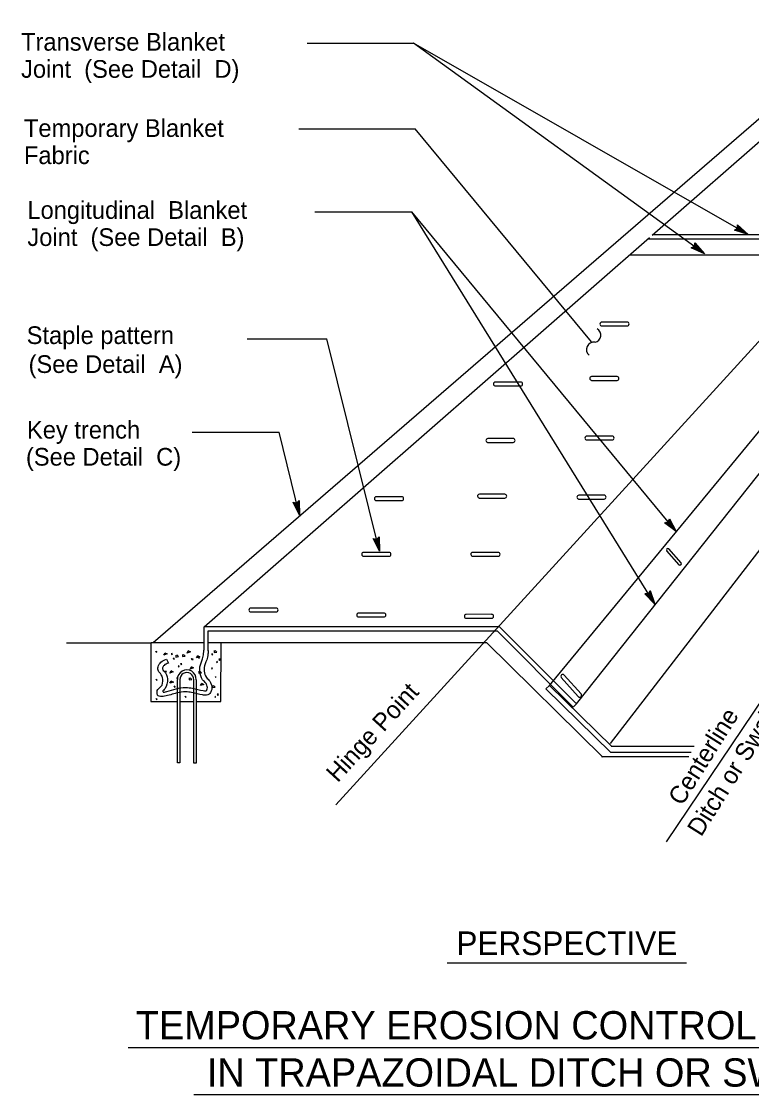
# Model space of a CAD drawing. Extents: x 6712486 to 6713732, y 1869200 to 1869925.
# Drawn here: x 6713055.2 to 6713312.8, y 1869202 to 1869580.8 of the extents above; entities that cross this region are included whole.
import ezdxf

# ---------------------------------------------------------------- set-up
doc = ezdxf.new("R2010")
doc.units = 0
for name, color, linetype in [('56 Stg 3 Anno', 7, 'Continuous'), ('57 Undefined', 7, 'Continuous'), ('60 Nongeo Data', 7, 'Continuous'), ('63 Undefined', 7, 'Continuous')]:
    doc.layers.add(name, color=color, linetype=linetype)

msp = doc.modelspace()

# ---------------------------------------------------------------- linework, layer by layer
at = {"layer": '56 Stg 3 Anno'}
for p, q in [((6713306.74, 1869507.11), (6713307.86, 1869507.74)), ((6713311.62, 1869505.59), (6713306.74, 1869507.11)), ((6713306.74, 1869507.11), (6713306.74, 1869507.11)), ((6713310.62, 1869506.17), (6713307.05, 1869507.28)), ((6713309.63, 1869506.74), (6713307.33, 1869507.45)), ((6713308.63, 1869507.31), (6713307.64, 1869507.62)), ((6713307.86, 1869507.74), (6713307.84, 1869509.04)), ((6713307.84, 1869509.04), (6713307.84, 1869509.04)), ((6713307.84, 1869509.04), (6713311.62, 1869505.59)), ((6713307.85, 1869508.7), (6713310.63, 1869506.16)), ((6713307.85, 1869508.02), (6713308.63, 1869507.31)), ((6713307.87, 1869508.34), (6713309.63, 1869506.74)), ((6713311.62, 1869505.59), (6713311.62, 1869505.59)), ((6713153.29, 1869406.53), (6713151.02, 1869411.12)), ((6713151.02, 1869411.12), (6713151.02, 1869411.12)), ((6713151.02, 1869411.12), (6713152.25, 1869410.73)), ((6713153.01, 1869407.65), (6713151.35, 1869411)), ((6713152.74, 1869408.76), (6713151.67, 1869410.92)), ((6713152.46, 1869409.88), (6713152.01, 1869410.81)), ((6713152.25, 1869410.73), (6713153.18, 1869411.65)), ((6713152.44, 1869410.93), (6713152.46, 1869409.88)), ((6713152.69, 1869411.14), (6713152.74, 1869408.76)), ((6713152.93, 1869411.4), (6713153.01, 1869407.65)), ((6713153.18, 1869411.65), (6713153.18, 1869411.65)), ((6713153.18, 1869411.65), (6713153.29, 1869406.53)), ((6713153.29, 1869406.53), (6713153.29, 1869406.53)), ((6713283.38, 1869404.07), (6713283.82, 1869405.29)), ((6713283.47, 1869404.32), (6713283.94, 1869403.39)), ((6713283.6, 1869404.62), (6713284.68, 1869402.5)), ((6713283.7, 1869404.96), (6713285.41, 1869401.61)), ((6713283.82, 1869405.29), (6713283.82, 1869405.29)), ((6713283.82, 1869405.29), (6713286.14, 1869400.73)), ((6713282.1, 1869403.87), (6713283.38, 1869404.07)), ((6713286.14, 1869400.73), (6713282.1, 1869403.87)), ((6713282.1, 1869403.87), (6713282.1, 1869403.87)), ((6713285.4, 1869401.62), (6713282.46, 1869403.91)), ((6713284.68, 1869402.5), (6713282.77, 1869403.98)), ((6713283.94, 1869403.39), (6713283.13, 1869404.02)), ((6713286.14, 1869400.73), (6713286.14, 1869400.73)), ((6713181.5, 1869393.77), (6713179.24, 1869398.35)), ((6713179.24, 1869398.35), (6713179.24, 1869398.35)), ((6713179.24, 1869398.35), (6713180.47, 1869397.97)), ((6713181.22, 1869394.89), (6713179.57, 1869398.23)), ((6713180.96, 1869396), (6713179.89, 1869398.16)), ((6713180.68, 1869397.12), (6713180.23, 1869398.04)), ((6713180.47, 1869397.97), (6713181.39, 1869398.88)), ((6713180.66, 1869398.17), (6713180.68, 1869397.12)), ((6713180.91, 1869398.38), (6713180.96, 1869396)), ((6713181.15, 1869398.64), (6713181.23, 1869394.88)), ((6713181.39, 1869398.88), (6713181.39, 1869398.88)), ((6713181.39, 1869398.88), (6713181.5, 1869393.77)), ((6713181.5, 1869393.77), (6713181.5, 1869393.77))]:
    msp.add_line(p, q, dxfattribs=at)
for centre, radius, start, end in [((6713257.03, 1869470.05), 2.57, 283.3074, 60.1497), ((6713257.11, 1869464.99), 2.59, 80.6529, 231.1528)]:
    msp.add_arc(centre, radius, start, end, dxfattribs=at)
at = {"layer": '57 Undefined'}
for p, q in [((6713205.42, 1869248.49), (6713289.79, 1869248.49)), ((6713092.76, 1869218.7), (6713401.4, 1869218.7)), ((6713115.97, 1869202.05), (6713377.19, 1869202.05))]:
    msp.add_line(p, q, dxfattribs=at)
at = {"layer": '60 Nongeo Data'}
for p, q in [((6713101.67, 1869361.64), (6713354.99, 1869580.77)), ((6713166.12, 1869304.3), (6713418.14, 1869580.63)), ((6713277.68, 1869505.33), (6713363.47, 1869580.38)), ((6713156.01, 1869573.15), (6713193.51, 1869573.15)), ((6713296.19, 1869498.8), (6713193.51, 1869573.15)), ((6713311.62, 1869505.59), (6713193.51, 1869573.15)), ((6713241.48, 1869346.43), (6713427.47, 1869571.97)), ((6713251.03, 1869340), (6713431.63, 1869567.55)), ((6713262.99, 1869325.95), (6713441.52, 1869557.72)), ((6713282.78, 1869291.27), (6713461.81, 1869557.71)), ((6713153.05, 1869542.9), (6713194.12, 1869542.9)), ((6713256.3, 1869467.65), (6713194.12, 1869542.9)), ((6713158.69, 1869513.54), (6713192.92, 1869513.54)), ((6713278.7, 1869375.13), (6713192.92, 1869513.54)), ((6713286.14, 1869400.73), (6713192.92, 1869513.54)), ((6713119.65, 1869367.1), (6713276.78, 1869504.55)), ((6713259.88, 1869473.31), (6713268.89, 1869473.31)), ((6713268.89, 1869474.68), (6713259.94, 1869474.68)), ((6713134.85, 1869468.78), (6713162.94, 1869468.78)), ((6713181.5, 1869393.77), (6713162.94, 1869468.78)), ((6713231.33, 1869453.52), (6713222.37, 1869453.52)), ((6713256.3, 1869454.06), (6713265.31, 1869454.06)), ((6713265.31, 1869455.44), (6713256.36, 1869455.43)), ((6713222.31, 1869452.15), (6713231.33, 1869452.15)), ((6713115.41, 1869435.81), (6713146.04, 1869435.81)), ((6713153.29, 1869406.53), (6713146.04, 1869435.81)), ((6713219.65, 1869432.21), (6713228.67, 1869432.21)), ((6713228.67, 1869433.58), (6713219.72, 1869433.58)), ((6713254.56, 1869433.08), (6713263.58, 1869433.08)), ((6713263.58, 1869434.45), (6713254.63, 1869434.45)), ((6713189.31, 1869413.03), (6713180.36, 1869413.03)), ((6713216.68, 1869412.56), (6713225.7, 1869412.56)), ((6713225.7, 1869413.93), (6713216.74, 1869413.93)), ((6713251.75, 1869412.21), (6713260.77, 1869412.21)), ((6713260.77, 1869413.58), (6713251.81, 1869413.58)), ((6713180.3, 1869411.66), (6713189.31, 1869411.66)), ((6713184.84, 1869393.4), (6713175.89, 1869393.39)), ((6713223.33, 1869393.4), (6713214.38, 1869393.39)), ((6713282.8, 1869393.96), (6713287.17, 1869389.05)), ((6713287.91, 1869389.71), (6713283.57, 1869394.59)), ((6713175.83, 1869392.03), (6713184.84, 1869392.03)), ((6713214.31, 1869392.03), (6713223.33, 1869392.03)), ((6713136.02, 1869372.39), (6713145.04, 1869372.39)), ((6713145.04, 1869373.76), (6713136.09, 1869373.76)), ((6713174.04, 1869370.6), (6713183.05, 1869370.6)), ((6713183.05, 1869371.97), (6713174.1, 1869371.97)), ((6713221.07, 1869371.53), (6713212.11, 1869371.52)), ((6713212.05, 1869370.16), (6713221.07, 1869370.16)), ((6713100.97, 1869361.58), (6713119.54, 1869361.58)), ((6713121.32, 1869361.58), (6713125.28, 1869361.58)), ((6713102.86, 1869358.46), (6713102.55, 1869358.32)), ((6713102.55, 1869358.32), (6713102.61, 1869358.37)), ((6713102.61, 1869358.37), (6713102.84, 1869358.03)), ((6713102.84, 1869358.03), (6713102.89, 1869358.49)), ((6713105.38, 1869357.15), (6713105.84, 1869357.88)), ((6713106.57, 1869357.55), (6713105.38, 1869357.15)), ((6713105.72, 1869358), (6713106.57, 1869357.55)), ((6713108.34, 1869357.7), (6713108.03, 1869357.56)), ((6713108.03, 1869357.56), (6713108.08, 1869357.61)), ((6713108.08, 1869357.61), (6713108.31, 1869357.28)), ((6713108.31, 1869357.28), (6713108.36, 1869357.73)), ((6713109.05, 1869356.02), (6713108.74, 1869355.88)), ((6713108.74, 1869355.88), (6713108.79, 1869355.94)), ((6713108.79, 1869355.94), (6713109.02, 1869355.6)), ((6713109.02, 1869355.6), (6713109.08, 1869356.05)), ((6713110.07, 1869357.09), (6713109.5, 1869356.92)), ((6713109.62, 1869357.04), (6713109.62, 1869356.47)), ((6713109.62, 1869356.47), (6713110.52, 1869356.59)), ((6713110.52, 1869356.59), (6713110.07, 1869357.09)), ((6713112.44, 1869357.26), (6713111.88, 1869357.09)), ((6713111.99, 1869357.21), (6713111.99, 1869356.64)), ((6713111.99, 1869356.64), (6713112.89, 1869356.76)), ((6713112.89, 1869356.76), (6713112.44, 1869357.26)), ((6713113.57, 1869357.88), (6713114.02, 1869358.62)), ((6713114.76, 1869358.28), (6713113.57, 1869357.88)), ((6713113.91, 1869358.73), (6713114.76, 1869358.28)), ((6713115.04, 1869355.97), (6713115.32, 1869355.57)), ((6713115.04, 1869355.97), (6713115.66, 1869355.8)), ((6713115.32, 1869355.57), (6713115.72, 1869355.63)), ((6713115.72, 1869355.63), (6713115.66, 1869355.8)), ((6713116.96, 1869356.14), (6713117.41, 1869356.87)), ((6713118.14, 1869356.53), (6713116.96, 1869356.14)), ((6713117.3, 1869356.98), (6713118.14, 1869356.53)), ((6713117.92, 1869356.39), (6713117.61, 1869356.25)), ((6713117.67, 1869356.3), (6713117.89, 1869355.97)), ((6713117.89, 1869355.97), (6713117.95, 1869356.42)), ((6713117.95, 1869356.42), (6713117.89, 1869356.36)), ((6713122.58, 1869357.58), (6713122.27, 1869357.44)), ((6713122.27, 1869357.44), (6713122.32, 1869357.5)), ((6713122.32, 1869357.5), (6713122.55, 1869357.16)), ((6713122.55, 1869357.16), (6713122.6, 1869357.61)), ((6713123.6, 1869358.65), (6713123.03, 1869358.48)), ((6713123.15, 1869358.59), (6713123.15, 1869358.03)), ((6713123.15, 1869358.03), (6713124.05, 1869358.14)), ((6713124.05, 1869358.14), (6713123.6, 1869358.65)), ((6713125.29, 1869355.66), (6713124.78, 1869355.66)), ((6713124.84, 1869355.72), (6713125.01, 1869355.21)), ((6713125.01, 1869355.21), (6713125.29, 1869355.66)), ((6713125.52, 1869358.76), (6713125.52, 1869358.2)), ((6713106.2, 1869351.5), (6713105.89, 1869351.36)), ((6713105.89, 1869351.36), (6713105.95, 1869351.42)), ((6713105.95, 1869351.42), (6713106.18, 1869351.08)), ((6713106.18, 1869351.08), (6713106.23, 1869351.53)), ((6713107.52, 1869350.8), (6713107.97, 1869351.54)), ((6713107.85, 1869351.65), (6713108.7, 1869351.2)), ((6713110.72, 1869353.33), (6713110.41, 1869353.19)), ((6713110.41, 1869353.19), (6713110.47, 1869353.25)), ((6713110.47, 1869353.25), (6713110.69, 1869352.91)), ((6713110.69, 1869352.91), (6713110.75, 1869353.36)), ((6713111.76, 1869354.11), (6713111.25, 1869354.11)), ((6713111.31, 1869354.16), (6713111.48, 1869353.66)), ((6713111.48, 1869353.66), (6713111.76, 1869354.11)), ((6713114.72, 1869352.22), (6713115.18, 1869352.96)), ((6713115.91, 1869352.62), (6713114.72, 1869352.22)), ((6713115.06, 1869353.07), (6713115.91, 1869352.62)), ((6713118.2, 1869351.35), (6713117.63, 1869351.18)), ((6713117.75, 1869351.29), (6713117.75, 1869350.73)), ((6713118.65, 1869350.84), (6713118.2, 1869351.35)), ((6713122.47, 1869352.63), (6713122.16, 1869352.49)), ((6713122.16, 1869352.49), (6713122.22, 1869352.54)), ((6713122.22, 1869352.54), (6713122.44, 1869352.2)), ((6713122.44, 1869352.2), (6713122.5, 1869352.66)), ((6713124.25, 1869354.89), (6713123.94, 1869354.75)), ((6713123.94, 1869354.75), (6713124, 1869354.8)), ((6713124, 1869354.8), (6713124.22, 1869354.47)), ((6713124.22, 1869354.47), (6713124.28, 1869354.92)), ((6713102.95, 1869348.57), (6713102.64, 1869348.43)), ((6713102.64, 1869348.43), (6713102.7, 1869348.49)), ((6713102.7, 1869348.49), (6713102.92, 1869348.15)), ((6713102.92, 1869348.15), (6713102.98, 1869348.6)), ((6713108.7, 1869351.2), (6713107.52, 1869350.8)), ((6713107.56, 1869347.19), (6713108.01, 1869347.92)), ((6713108.75, 1869347.58), (6713107.56, 1869347.19)), ((6713107.9, 1869348.03), (6713108.75, 1869347.58)), ((6713110.27, 1869349.17), (6713109.95, 1869349.03)), ((6713109.95, 1869349.03), (6713110.01, 1869349.08)), ((6713110.01, 1869349.08), (6713110.24, 1869348.74)), ((6713110.18, 1869319.09), (6713110.17, 1869348.48)), ((6713110.24, 1869348.74), (6713110.29, 1869349.19)), ((6713111.02, 1869348.48), (6713111.04, 1869319.09)), ((6713114.81, 1869349.04), (6713114.25, 1869348.87)), ((6713114.36, 1869348.98), (6713114.36, 1869348.42)), ((6713114.36, 1869348.42), (6713115.26, 1869348.53)), ((6713115.26, 1869348.53), (6713114.81, 1869349.04)), ((6713115.94, 1869319.06), (6713115.93, 1869348.41)), ((6713116.79, 1869348.36), (6713116.77, 1869319.06)), ((6713117.75, 1869350.73), (6713118.65, 1869350.84)), ((6713123.51, 1869349.59), (6713123.73, 1869349.25)), ((6713245.61, 1869349.24), (6713251.61, 1869342.51)), ((6713252.63, 1869343.42), (6713246.68, 1869350.11)), ((6713109.25, 1869346.13), (6713108.94, 1869345.99)), ((6713109, 1869346.05), (6713109.22, 1869345.71)), ((6713109.22, 1869345.71), (6713109.28, 1869346.16)), ((6713109.28, 1869346.16), (6713109.22, 1869346.11)), ((6713110.3, 1869345.2), (6713110.24, 1869345.15)), ((6713118.31, 1869346.37), (6713118.77, 1869347.1)), ((6713119.5, 1869346.77), (6713118.31, 1869346.37)), ((6713118.65, 1869347.22), (6713119.5, 1869346.77)), ((6713123, 1869346.31), (6713122.43, 1869346.14)), ((6713122.55, 1869346.26), (6713122.55, 1869345.69)), ((6713122.55, 1869345.69), (6713123.45, 1869345.81)), ((6713123.45, 1869345.81), (6713123, 1869346.31)), ((6713102.92, 1869341.74), (6713102.6, 1869341.6)), ((6713102.6, 1869341.6), (6713102.66, 1869341.66)), ((6713102.66, 1869341.66), (6713102.89, 1869341.32)), ((6713102.89, 1869341.32), (6713102.94, 1869341.77)), ((6713113.13, 1869342.57), (6713112.82, 1869342.43)), ((6713112.82, 1869342.43), (6713112.88, 1869342.48)), ((6713112.88, 1869342.48), (6713113.1, 1869342.14)), ((6713113.1, 1869342.14), (6713113.16, 1869342.6)), ((6713123.65, 1869342.55), (6713123.34, 1869342.41)), ((6713123.34, 1869342.41), (6713123.4, 1869342.47)), ((6713123.4, 1869342.47), (6713123.62, 1869342.13)), ((6713123.62, 1869342.13), (6713123.68, 1869342.58)), ((6713124.69, 1869343.33), (6713124.19, 1869343.33)), ((6713124.24, 1869343.38), (6713124.41, 1869342.88)), ((6713124.41, 1869342.88), (6713124.69, 1869343.33)), ((6713249.85, 1869338.72), (6713251.03, 1869340)), ((6713263.26, 1869324.99), (6713292.55, 1869324.99)), ((6713259.88, 1869321.32), (6713290.63, 1869321.32)), ((6713263.11, 1869322.86), (6713291.43, 1869322.86)), ((6713111.04, 1869319.09), (6713110.18, 1869319.09)), ((6713116.77, 1869319.06), (6713115.94, 1869319.06))]:
    msp.add_line(p, q, dxfattribs=at)
for points in [[(6713276.29, 1869504.05), (6713348.67, 1869504.05), (6713377.77, 1869475.13)], [(6713277.96, 1869505.59), (6713349.9, 1869505.59), (6713379, 1869476.67)], [(6713269.81, 1869498.45), (6713343.95, 1869498.45), (6713372.53, 1869470.06)], [(6713119.61, 1869358.91), (6713119.6, 1869367.06)], [(6713251.03, 1869340), (6713223.86, 1869367.14), (6713119.65, 1869367.1)], [(6713121.07, 1869358.63), (6713121.06, 1869365.72), (6713222.96, 1869365.69), (6713249.85, 1869338.72)], [(6713071.04, 1869361.53), (6713100.82, 1869361.53), (6713100.79, 1869340.77), (6713110.16, 1869340.77)], [(6713116.77, 1869340.76), (6713125.55, 1869340.78), (6713125.58, 1869361.59)], [(6713125.33, 1869361.57), (6713219.29, 1869361.6), (6713260.33, 1869321.16)], [(6713241.48, 1869346.43), (6713240.24, 1869345.18), (6713263.1, 1869322.76)], [(6713241.48, 1869346.43), (6713263.47, 1869324.9)], [(6713111.03, 1869340.76), (6713115.95, 1869340.76)]]:
    msp.add_lwpolyline(points, dxfattribs=at)
for centre, radius, start, end in [((6713259.97, 1869474), 0.685, 92.5576, 270), ((6713268.89, 1869474), 0.686, 270, 90), ((6713222.4, 1869452.83), 0.685, 92.5576, 270), ((6713231.32, 1869452.83), 0.686, 270, 90), ((6713256.39, 1869454.75), 0.685, 92.5576, 270), ((6713265.31, 1869454.75), 0.686, 270, 90), ((6713219.75, 1869432.9), 0.685, 92.5576, 270), ((6713228.67, 1869432.9), 0.686, 270, 90), ((6713254.66, 1869433.76), 0.685, 92.5576, 270), ((6713263.58, 1869433.76), 0.686, 270, 90), ((6713180.39, 1869412.35), 0.685, 92.5576, 270), ((6713189.31, 1869412.35), 0.686, 270, 90), ((6713216.77, 1869413.24), 0.685, 92.5576, 270), ((6713225.7, 1869413.24), 0.686, 270, 90), ((6713251.84, 1869412.9), 0.685, 92.5576, 270), ((6713260.76, 1869412.9), 0.686, 270, 90), ((6713175.92, 1869392.71), 0.685, 92.5576, 270), ((6713184.84, 1869392.71), 0.686, 270, 90), ((6713214.41, 1869392.71), 0.685, 92.5576, 270), ((6713223.33, 1869392.71), 0.686, 270, 90), ((6713283.21, 1869394.24), 0.5, 44.2481, 221.6905), ((6713287.54, 1869389.38), 0.5, 221.6905, 41.6905), ((6713136.12, 1869373.07), 0.685, 92.5576, 270), ((6713145.04, 1869373.07), 0.686, 270, 90), ((6713174.13, 1869371.29), 0.685, 92.5576, 270), ((6713183.05, 1869371.29), 0.686, 270, 90), ((6713212.14, 1869370.84), 0.685, 92.5576, 270), ((6713221.07, 1869370.84), 0.686, 270, 90), ((6713246.19, 1869349.63), 0.685, 44.2481, 221.6905), ((6713252.12, 1869342.97), 0.686, 221.6905, 41.6905)]:
    msp.add_arc(centre, radius, start, end, dxfattribs=at)
for centre, major_axis in [((6713113.48, 1869348.6), (0, -3.31)), ((6713113.48, 1869348.57), (0, -2.45))]:
    msp.add_ellipse(centre, major_axis=major_axis, ratio=0.999991, start_param=1.510257, end_param=4.748244, dxfattribs=at)
at = {"layer": '63 Undefined'}
for p, q in [((6713291.49, 1869500.84), (6713291.49, 1869500.84)), ((6713292.8, 1869502.64), (6713292.8, 1869502.64)), ((6713296.19, 1869498.8), (6713296.19, 1869498.8)), ((6713275.12, 1869378.8), (6713275.12, 1869378.8)), ((6713277.01, 1869379.97), (6713277.01, 1869379.97)), ((6713278.7, 1869375.13), (6713278.7, 1869375.13)), ((6713106.33, 1869355.65), (6713107.01, 1869354.28))]:
    msp.add_line(p, q, dxfattribs=at)
for points in [[(6713292.8, 1869502.64), (6713296.19, 1869498.8), (6713291.49, 1869500.84), (6713291.81, 1869500.97), (6713295.25, 1869499.48), (6713292.77, 1869502.29), (6713292.74, 1869501.95), (6713294.33, 1869500.15), (6713292.13, 1869501.11), (6713292.44, 1869501.24), (6713293.4, 1869500.83), (6713292.71, 1869501.61), (6713292.68, 1869501.34), (6713291.49, 1869500.84), (6713292.68, 1869501.34)], [(6713277.01, 1869379.97), (6713278.7, 1869375.13), (6713275.12, 1869378.8), (6713275.47, 1869378.8), (6713278.08, 1869376.12), (6713276.86, 1869379.66), (6713276.7, 1869379.36), (6713277.49, 1869377.09), (6713275.81, 1869378.81), (6713276.16, 1869378.81), (6713276.88, 1869378.07), (6713276.54, 1869379.05), (6713276.42, 1869378.81), (6713275.12, 1869378.8), (6713276.42, 1869378.81)]]:
    msp.add_lwpolyline(points, close=True, dxfattribs=at)
for points in [[(6713107.01, 1869354.28), (6713105.46, 1869353.51), (6713104.96, 1869352.66), (6713105, 1869352.03), (6713105.47, 1869351.48), (6713106.63, 1869348.73), (6713105.76, 1869345.26), (6713105.23, 1869344.67), (6713105.07, 1869344.52), (6713105.11, 1869344.12), (6713105.26, 1869344.06), (6713105.58, 1869344.1), (6713106.44, 1869344.33), (6713109.69, 1869345.27), (6713113.13, 1869345.7), (6713115.46, 1869345.46), (6713119.23, 1869344.59), (6713120.19, 1869344.52), (6713120.43, 1869344.61), (6713120.54, 1869344.75), (6713120.61, 1869344.88), (6713120.61, 1869346.51), (6713120.32, 1869347.08), (6713119.06, 1869348.46), (6713118.12, 1869351.28), (6713118.12, 1869352.96), (6713119.03, 1869355.82), (6713119.43, 1869357.7), (6713119.51, 1869358.84)], [(6713121.03, 1869358.74), (6713120.95, 1869357.49), (6713120.51, 1869355.43), (6713119.65, 1869352.72), (6713119.65, 1869351.53), (6713120.4, 1869349.26), (6713121.59, 1869347.96), (6713122.14, 1869346.87), (6713122.14, 1869344.49), (6713121.81, 1869343.9), (6713121.34, 1869343.32), (6713120.4, 1869342.97), (6713119, 1869343.08), (6713115.21, 1869343.95), (6713113.15, 1869344.16), (6713109.98, 1869343.77), (6713105.6, 1869342.59), (6713103.76, 1869342.63), (6713103.21, 1869343.03), (6713103.09, 1869343.3), (6713103, 1869343.68), (6713103.08, 1869344.6), (6713104.38, 1869346.01), (6713105.03, 1869348.61), (6713104.16, 1869350.66), (6713103.51, 1869351.42), (6713103.4, 1869353.02), (6713104.38, 1869354.67), (6713106.33, 1869355.65)]]:
    msp.add_spline(points, degree=3, dxfattribs=at)

# ---------------------------------------------------------------- texts
at = {"layer": '57 Undefined'}
for s, height, p in [('PERSPECTIVE', 8.3268, (6713208.62, 1869251.28)), ('TEMPORARY EROSION CONTROL BLANKET', 9.9921, (6713095.5, 1869221.5)), ('IN TRAPAZOIDAL DITCH OR SWALE', 9.9921, (6713120.56, 1869204.84))]:
    msp.add_text(s, height=height, dxfattribs=at).set_placement(p)
at = {"layer": '60 Nongeo Data'}
for s, height, p in [('Transverse Blanket ', 6.2451, (6713055.02, 1869570.46)), ('Joint  (See Detail  D)', 6.2451, (6713055.02, 1869560.89)), ('Temporary Blanket ', 6.2451, (6713056.03, 1869540.02)), ('Fabric', 6.245, (6713056.03, 1869530.44)), ('Longitudinal  Blanket ', 6.2451, (6713057.25, 1869511.11)), ('Joint  (See Detail  B)', 6.2451, (6713057.25, 1869501.54)), ('Staple pattern', 6.2451, (6713056.99, 1869466.93)), ('(See Detail  A)', 6.2451, (6713057.67, 1869456.72)), ('Key trench', 6.245, (6713057.11, 1869433.55)), ('(See Detail  C)', 6.2451, (6713056.74, 1869424.01))]:
    msp.add_text(s, height=height, dxfattribs=at).set_placement(p)
for s, height, rotation, p in [('Hinge Point', 6.2451, 47.6341, (6713166.72, 1869311.89)), ('Ditch or Swale', 6.2451, 57.8381, (6713294.99, 1869292.77)), ('Centerline', 6.245, 57.8381, (6713288.26, 1869303.66))]:
    msp.add_text(s, height=height, rotation=rotation, dxfattribs=at).set_placement(p)

doc.saveas('drawing.dxf')
